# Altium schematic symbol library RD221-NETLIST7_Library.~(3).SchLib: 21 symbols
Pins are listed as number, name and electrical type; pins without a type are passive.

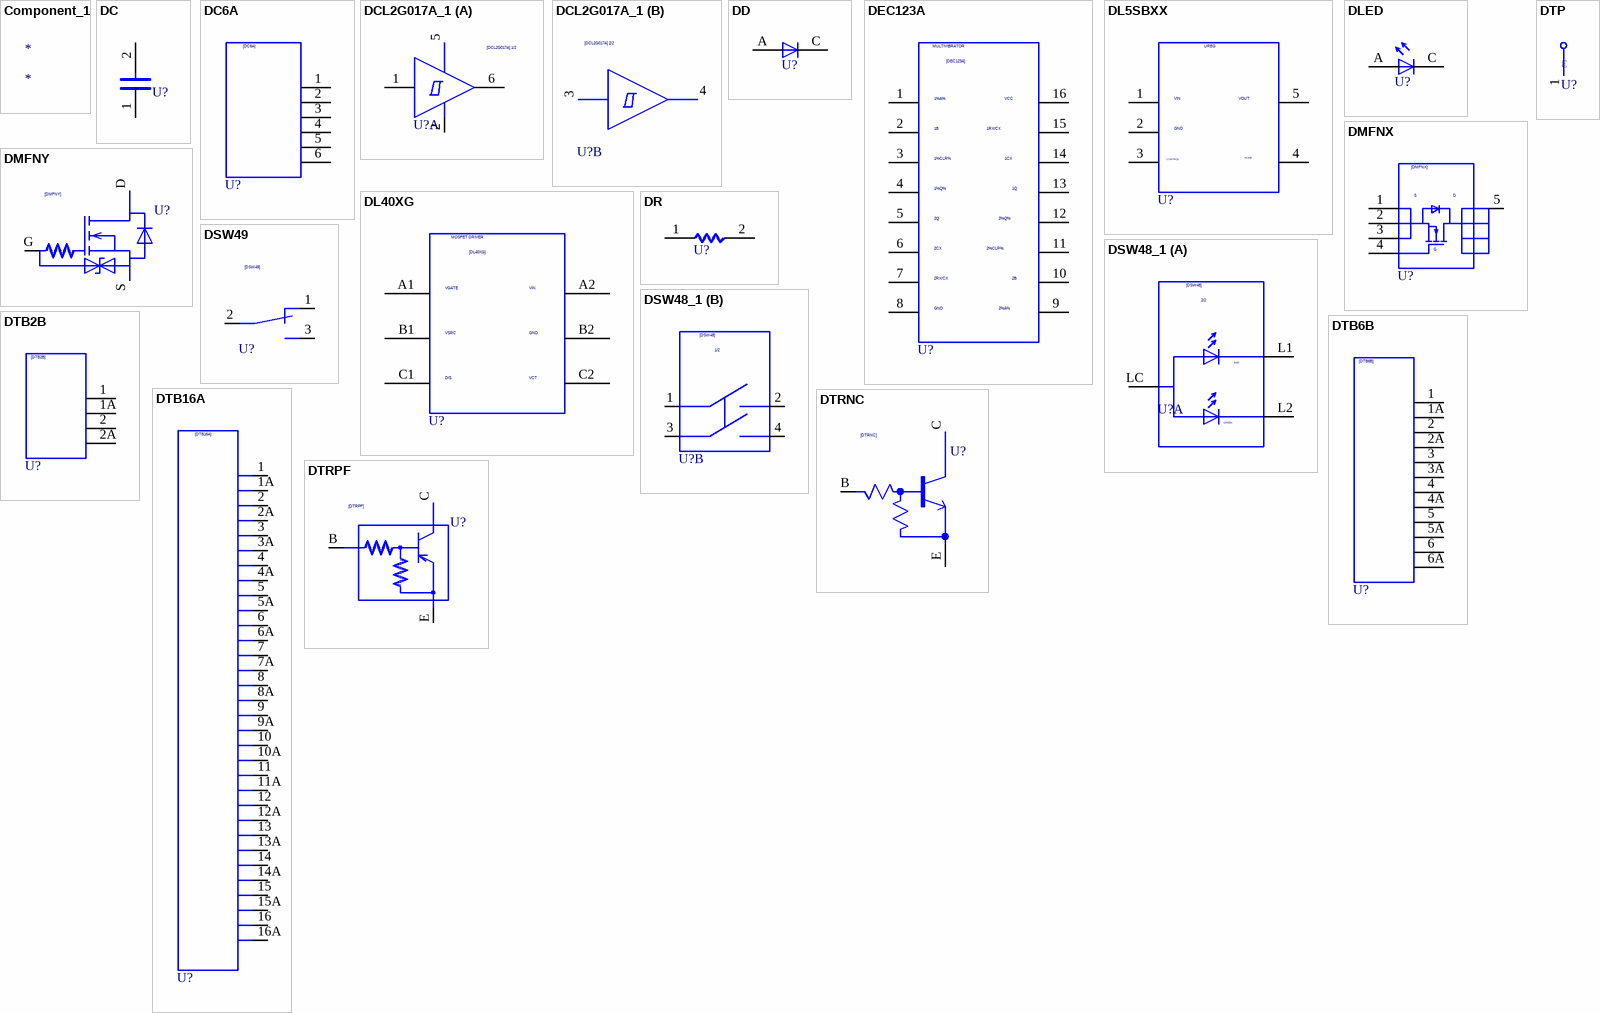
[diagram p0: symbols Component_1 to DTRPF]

## Component_1
designator *

## DC
designator U?  (value not drawn)
OriginalSymbolOrigin: (2540,7620); Altium-Right: 20; Altium-Bottom: 10
pins: 1, 2

## DC6A
designator U?  (value not drawn)
SAVEAREA0: -19103,0,39483,27940; SAVECOUNT: 24; TIME: 13:28:28; UPDATEUSER: e1023210; UPDATETIME: 18:37:18; OriginalSymbolOrigin: (2540,25400); Altium-Right: 50; Altium-Bottom: 90
pins: 1, 2, 3, 4, 5, 6

## DCL2G017A_1
designator U?  (value not drawn)
TIME: 14:48:25; UPDATEUSER: w90028dm; UPDATETIME: 11:00:47; SAVECOUNT: 12; SAVEAREA0: -27668,-19920,47920,35415; OriginalSymbolOrigin: (0,12700); Altium-Right: 40; Altium-Bottom: 50; Altium-Right1: 80
part A pins: 1, 2, 5, 6
part B pins: 3, 4

## DD
designator U?  (value not drawn)
SAVEAREA0: -225,-91,12804,7836; SAVECOUNT: 3; TIME: 14:49:55; UPDATEUSER: 19870035; UPDATETIME: 14:20:16; OriginalSymbolOrigin: (5080,5080); Altium-Right: 10; Altium-Bottom: 20
pins: A, C

## DEC123A
designator U?  (value not drawn)
SAVEAREA0: -51950,-1012,82634,54279; SAVECOUNT: 6; TIME: 14:53:14; UPDATEUSER: w90028dm; UPDATETIME: 14:48:13; OriginalSymbolOrigin: (5080,50800); Altium-Right: 80; Altium-Bottom: 200
pins: 1, 2, 3, 4, 5, 6, 7, 8, 9, 10, 11, 12, 13, 14, 15, 16

## DL5SBXX
designator U?  (value not drawn)
SAVEAREA0: -63304,-44289,95072,71651; SAVECOUNT: 23; TIME: 15:23:15; UPDATEUSER: t5459927; UPDATETIME: 14:43:50; OriginalSymbolOrigin: (5080,25400); Altium-Right: 80; Altium-Bottom: 100
pins: 1, 2, 3, 4, 5

## DL40XG
designator U?  (value not drawn)
SAVEAREA0: -42934,-29232,81850,62118; TIME: 11:49:52; UPDATEUSER: w90028dm; UPDATETIME: 09:11:31; SAVECOUNT: 26; OriginalSymbolOrigin: (7620,30480); Altium-Right: 90; Altium-Bottom: 120
pins: A1, A2, B1, B2, C1, C2

## DLED
designator U?  (value not drawn)
SAVEAREA0: -6799,-183,19247,15664; TIME: 14:49:55; UPDATEUSER: fukuda-y; UPDATETIME: 13:54:07; SAVECOUNT: 4; OriginalSymbolOrigin: (5080,7620); Altium-Right: 10; Altium-Bottom: 30
pins: A, C

## DMFNX
designator U?  (value not drawn)
SAVEAREA0: -12700,-263,35150,23556; TIME: 18:57:44; UPDATEUSER: 19990028; UPDATETIME: 11:40:13; SAVECOUNT: 15; OriginalSymbolOrigin: (5080,20320); Altium-Right: 60; Altium-Bottom: 70
pins: 1, 2, 3, 4, 5

## DMFNY
designator U?  (value not drawn)
PARTS: 1; SAVECOUNT: 28; SAVEAREA0: -23889,-10269,46852,25387; TIME: 08:01:03; UPDATEUSER: w90028dm; UPDATETIME: 15:04:53; HETERO: RN4905_1,RN4905_2; FUNCTION: PNP&NPN_PCT; LEVEL: STD; P/D_NUM: TOSHIBA; PKG_TYPE: 2-2J1A; DEVICE: RN4905; DEVICENAME: RN49A1FE(TE85L); OriginalSymbolOrigin: (2540,15240); Altium-Right: 80; Altium-Bottom: 60
pins: D, G, S

## DR
designator U?  (value not drawn)
OriginalSymbolOrigin: (5080,5080); Altium-Right: 20
pins: 1, 2

## DSW48_1
designator U?  (value not drawn)
PARTS: 1; SAVECOUNT: 17; SAVEAREA0: -14290,-6784,35003,29302; TIME: 19:37:19; UPDATEUSER: w90028dm; UPDATETIME: 08:14:33; OriginalSymbolOrigin: (2540,20320); HETERO: RN4905_1,RN4905_2; FUNCTION: PNP&NPN_PCT; LEVEL: STD; P/D_NUM: TOSHIBA; PKG_TYPE: 2-2J1A; DEVICE: RN4905; DEVICENAME: RN2104; CLASS: DISCRETE; Altium-Right: 70; Altium-Bottom: 110; Altium-Right1: 60; Altium-Bottom1: 80
part A pins: L1, L2, LC
part B pins: 1, 2, 3, 4

## DSW49
designator U?  (value not drawn)
SAVEAREA0: -42205,-15236,59041,26359; TIME: 14:45:03; UPDATEUSER: w90028dm; UPDATETIME: 17:53:32; SAVECOUNT: 4; OriginalSymbolOrigin: (2540,10160); Altium-Right: 40
pins: 1, 2, 3

## DTB2B
designator U?  (value not drawn)
SAVEAREA0: -49339,-13811,66103,33616; TIME: 10:12:24; UPDATEUSER: w90028dm; UPDATETIME: 11:01:13; SAVECOUNT: 5; OriginalSymbolOrigin: (0,17780); Altium-Right: 40; Altium-Bottom: 70
pins: 1, 1A, 2, 2A

## DTB6B
designator U?  (value not drawn)
SAVEAREA0: -69082,-11475,84961,51811; TIME: 10:12:24; UPDATEUSER: w90028dm; UPDATETIME: 11:01:53; SAVECOUNT: 6; OriginalSymbolOrigin: (0,38100); Altium-Right: 40; Altium-Bottom: 150
pins: 1, 1A, 2, 2A, 3, 3A, 4, 4A, 5, 5A, 6, 6A

## DTB16A
designator U?  (value not drawn)
SAVEAREA0: -110709,-1964,126601,95531; TIME: 12:01:18; UPDATEUSER: w90028dm; UPDATETIME: 09:06:25; SAVECOUNT: 20; OriginalSymbolOrigin: (0,91440); Altium-Right: 50; Altium-Bottom: 360
pins: 1, 1A, 2, 2A, 3, 3A, 4, 4A, 5, 5A, 6, 6A, 7, 7A, 8, 8A, 9, 9A, 10, 10A, 11, 11A, 12, 12A, 13, 13A, 14, 14A, 15, 15A, 16, 16A

## DTP
designator U?  (value not drawn)
TIME: 16:12:21; UPDATEUSER: fukuda-y; UPDATETIME: 16:18:11; SAVECOUNT: 2; SAVEAREA0: -242,-92,12810,7836; OriginalSymbolOrigin: (0,7620); Altium-Right: 20; Altium-Bottom: 30
pins: 1

## DTRNC
designator U?  (value not drawn)
SAVEAREA0: -25957,-6856,48160,30039; TIME: 14:43:11; UPDATEUSER: w90028dm; UPDATETIME: 10:13:46; SAVECOUNT: 5; OriginalSymbolOrigin: (2540,22860); Altium-Right: 70
pins: B, C, E

## DTRPF
designator U?  (value not drawn)
PARTS: 1; HETERO: RN4905_1,RN4905_2; FUNCTION: PNP&NPN_PCT; LEVEL: STD; P/D_NUM: TOSHIBA; PKG_TYPE: 2-2J1A; DEVICE: RN4905; SAVECOUNT: 12; SAVEAREA0: -44788,-13627,70567,33764; DEVICENAME: RN2104; TIME: 19:37:19; UPDATEUSER: w90028dm; UPDATETIME: 15:25:57; OriginalSymbolOrigin: (2540,20320); Altium-Right: 70
pins: B, C, E

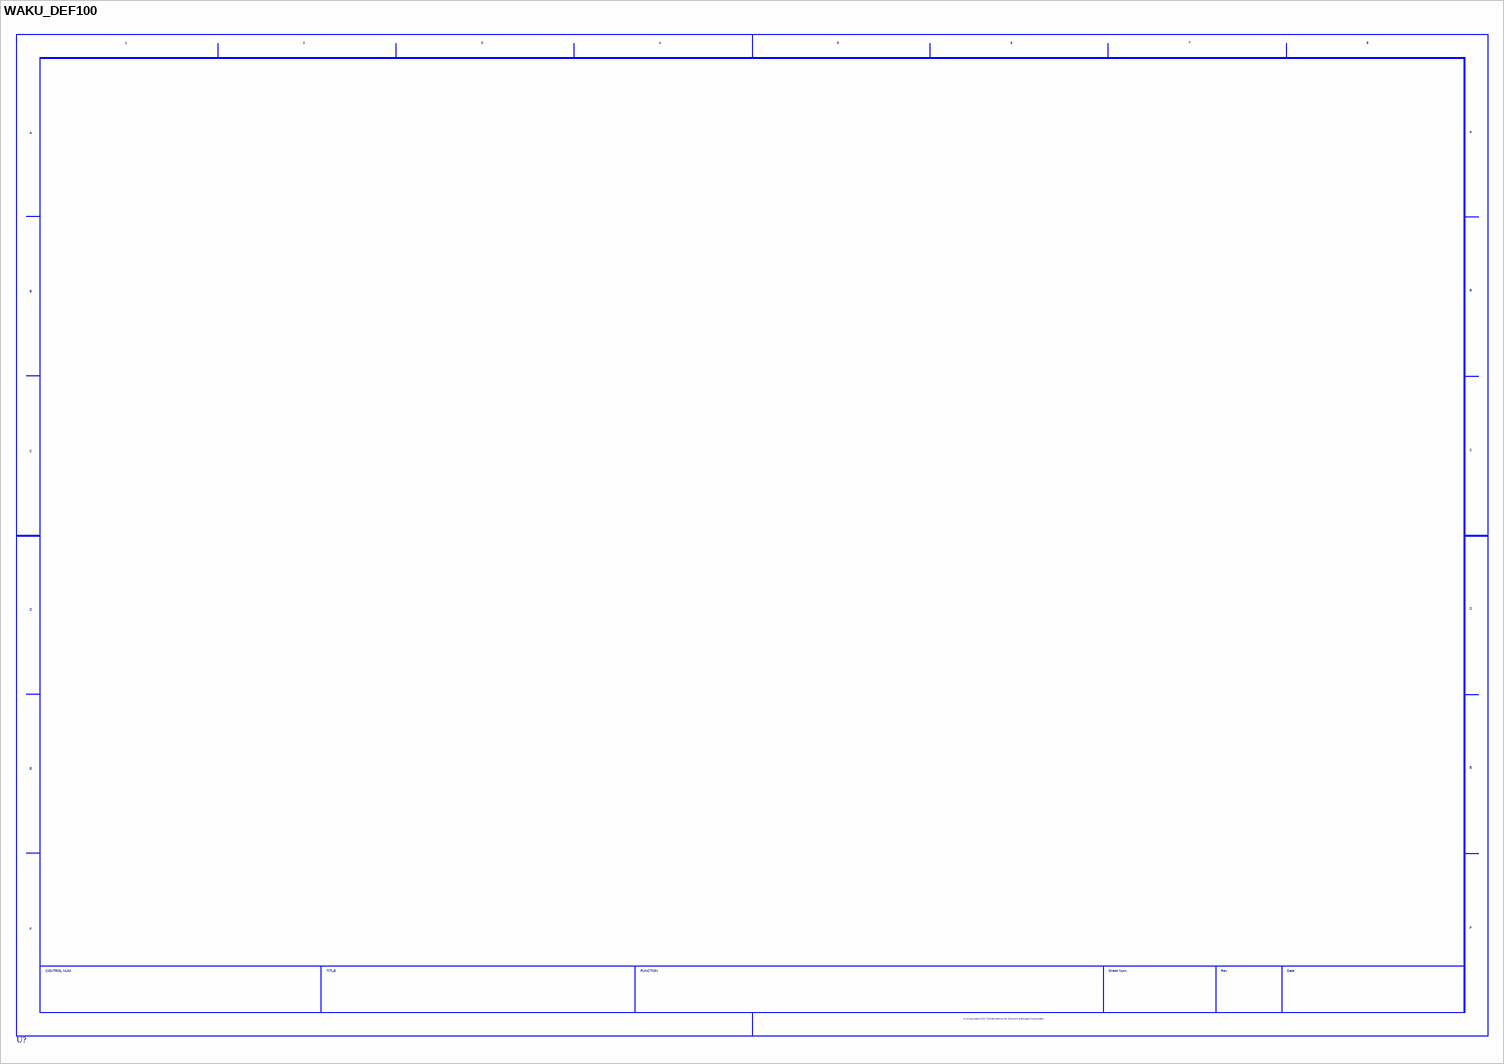
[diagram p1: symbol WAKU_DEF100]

## WAKU_DEF100
designator U?  (value not drawn)
PLOTTIME: HH:MM; SAVEAREA0: 331184,2849,387656,28880; TIME: 14:30:25; UPDATEUSER: t5459927; UPDATETIME: 15:18:07; SAVECOUNT: 7; OriginalSymbolOrigin: (10160,284480); Altium-Right: 1570; Altium-Bottom: 1070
